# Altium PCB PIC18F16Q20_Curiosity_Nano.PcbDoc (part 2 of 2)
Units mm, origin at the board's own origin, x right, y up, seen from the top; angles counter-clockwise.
Board outline 50.8 x 20.32 mm, 4 copper layers (Top Layer, Gnd Plane, Pwr Plane, Bottom Layer), stack 1.574 mm thick; 77 components, 73 nets, 345 pads, 157 vias.
Unrouted connection lines stored in the file: 1.
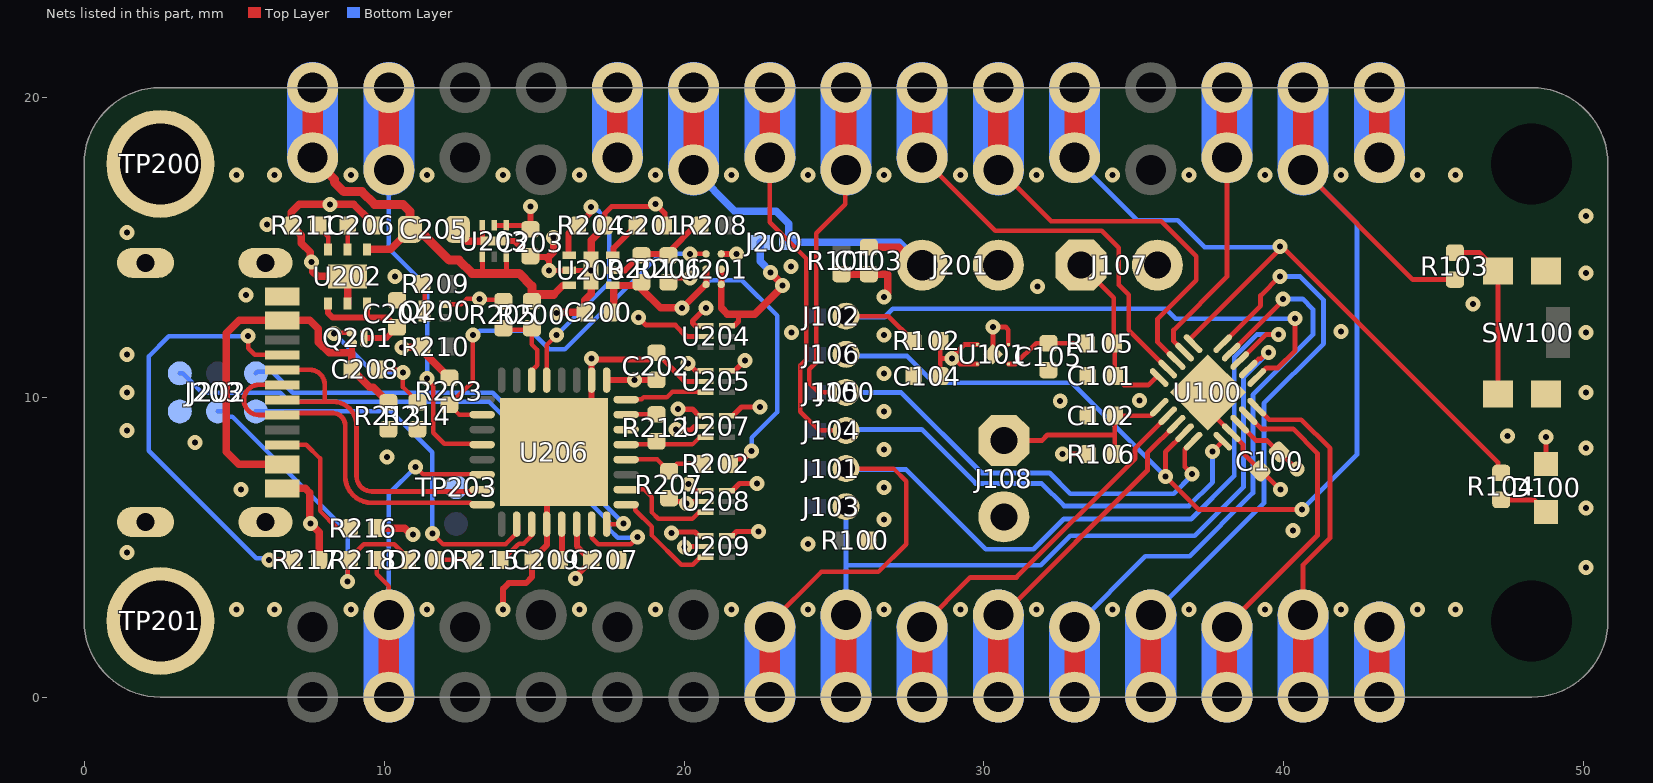
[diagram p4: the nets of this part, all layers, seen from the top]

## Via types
v1: diameter 0.5, hole 0.2, Top Layer to Bottom Layer, 147 vias
v2: diameter 0.5, hole 0.2, Top Layer to Bottom Layer, tented both sides, 8 vias
v3: diameter 0.5, hole 0.2, Top Layer to Bottom Layer, tented top, 2 vias

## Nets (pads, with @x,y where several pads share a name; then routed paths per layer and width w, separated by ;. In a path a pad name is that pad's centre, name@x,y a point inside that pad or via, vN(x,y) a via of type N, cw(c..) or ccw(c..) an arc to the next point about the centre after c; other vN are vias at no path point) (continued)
GND: C100.2 C101.2 C102.2 C103.1 C104.1 C105.1 C200.1 C201.2 C202.1 C203.1 C204.1 C205.1 C206.1 C207.2 C209.1 J100.15 J100.16 J100.26 J107.2 J108.2 J202.2 J203.1 J203.2 J203.3 J203.4 J203.A1/B12 J203.B1/A12 Q200.2 R100.2 R101.2 R203.2 R204.2 R205.1 R206.1 R207.1 R210.2 R211.2 R213.2 R214.2 R216.2 R217.2 SW100.1 SW100.2 TP200.1 TP201.1 TP203.1 U100.17 U100.21 U101.2 U101.5 U200.2 U200.7 U201.C1 U202.5 U202.7 U203.3 U203.7 U204.2 U205.2 U206.10 U206.28 U206.33 U207.2 U208.2 U209.2 | length 60
  Top Layer w0.15: Q200.2@12.04,13.1 12.575,13.1 12.75,13.275 v1(13.19,13.275) 13.215,13.25 R205.1@13.979,13.25
  Top Layer w0.16: U101.5@30.297,11.433 v1@30.297,12.325 ; v1(30.306,12.342) 30.717,12.342 30.81,12.248 U101.2@30.81,11.758 ; U100.21@37.465,10.16 37.465,9.594 38.63,8.429 38.63,8.154 39.86,6.924 v1(39.889,6.924)
  Top Layer w0.166: v1(18.48,12.65) 18.73,12.4 19.71,12.4 20.085,12.025 U204.2@20.729,12.025 ; C202.1@19.058,11.5 20.033,10.525 U205.2@20.729,10.525 ; v1(19.734,8.925) 19.759,8.9 19.804,8.9 20.217,8.9 20.343,9.025 U207.2@20.729,9.025 ; v1@20.13,5.025 U209.2@20.729,5.025 ; v1@20.155,6.525 U208.2@20.729,6.525
  Top Layer w0.175: U203.3@13.279,15.725 13.279,15.2 U203.7@13.679,15.2 ; v1(15.505,14.225) U200.2@16.18,14.225 v1(16.905,14.225) ; R204.2@17.355,15.725 17.355,16.122 17.59,16.357 18.89,16.357 18.969,16.436 v1(19.057,16.436) 19.355,16.138 C201.2@19.355,15.725 ; R206.1@19.48,13.775 19.68,13.975 v1(20.199,13.975) ; R207.1@19.555,6.525 19.559,6.521 19.861,6.521 19.932,6.45 v1(20.08,6.45) v1@20.155,6.525 ; v1(20.023,4.998) 20.103,4.998 v1@20.13,5.025 ; v1@20.089,5.025 v1@20.13,5.025 ; v1@20.125,5.02 v1@20.13,5.025
  Top Layer w0.2: U203.7@13.679,15.2 14.354,15.2 14.879,14.675 15.38,14.675 15.505,14.55 ; v1(13.97,2.921) 13.97,3.615 14.155,3.8 14.732,3.8 14.93,3.998 14.93,4.575 15.424,5.069 15.424,7.909 U206.33@15.679,8.164 ; v1(15.505,14.225) 15.505,14.55 ; 15.505,14.705 15.505,14.55 ; U206.33@15.689,8.174 16.916,9.401 16.916,11.112 17.063,11.259 18.817,11.259 C202.1@19.058,11.5 ; U201.C1@21.242,14.775 v1(21.755,14.775)
  Top Layer w0.25: J203.A1/B12@6.39,13.36 J203.A1/B12@6.665,13.36 ; J203.B1/A12@6.665,6.96 7.368,6.96 7.515,6.814 7.515,5.821 7.844,5.493 R217.2@7.844,4.575 ; U202.5@8.785,13.128 U202.7@8.785,14.028 7.784,14.028 7.627,14.186 7.627,14.452 7.535,14.544 7.535,14.84 7.246,15.128 7.246,15.393 7.081,15.558 7.062,15.558 6.913,15.707 6.913,16.168 7.172,16.426 v1(8.19,16.426) 8.192,16.424 8.986,16.424 9.518,15.892 9.536,15.892 9.685,15.743 C206.1@9.685,15.725 ; R216.2@9.752,5.633 10.684,5.633 10.892,5.425 v2(10.96,5.425) ; v1(10.599,11.649) 10.617,11.667 11.248,11.667 R210.2@11.265,11.684 11.407,11.542 11.407,11.412 12.008,10.811 12.008,10.793 12.157,10.644 R203.2@12.175,10.644 ; C205.1@12.356,15.597 12.754,15.2 U203.7@13.279,15.2 ; 15.505,14.705 15.655,14.855 v1(15.655,15.325) ; v1(15.755,12.8) 15.782,12.827 C200.1@16.695,12.827 16.695,13.233 16.905,13.443 v1(16.905,14.225) 16.905,15.225 R204.2@17.405,15.725 ; R101.2@25.248,14.104 C103.1@26.162,14.104 26.794,14.104 26.794,13.459 v1(26.67,13.335)
  other v1: 5.08,2.921 6.35,2.921 8.89,2.921 11.43,2.921 16.51,2.921 19.05,2.921 21.59,2.921 24.13,2.921 26.67,2.921 29.21,2.921 31.75,2.921 34.29,2.921 36.83,2.921 39.37,2.921 41.91,2.921 44.45,2.921 45.72,2.921 50.065,4.321 1.429,4.826 24.141,5.102 40.304,5.559 7.544,5.792 26.67,5.915 50.065,6.306 26.67,6.985 26.67,8.255 50.065,8.3 47.45,8.701 1.429,8.89 26.67,9.525 32.543,9.871 35.179,9.882 1.429,10.16 50.065,10.15 26.67,10.795 16.913,11.284 1.429,11.43 26.67,12.065 23.58,12.152 50.065,12.15 41.9,12.192 46.3,13.113 5.39,13.413 31.78,13.694 10.366,14.025 50.065,14.133 23.565,14.353 7.579,14.5 1.429,15.494 6.1,15.755 50.065,16.045 5.08,17.399 6.35,17.399 8.89,17.399 11.43,17.399 13.97,17.399 16.51,17.399 19.05,17.399 21.59,17.399 24.13,17.399 26.67,17.399 29.21,17.399 31.75,17.399 34.29,17.399 36.83,17.399 39.37,17.399 41.91,17.399 44.45,17.399 45.72,17.399
  other v2: 5.235,6.924 10.093,8.006 3.701,8.493
ID_SYS: J100.2 R218.1 U206.22 | length 9.6
  Top Layer w0.15: R218.1@9.748,4.513 9.748,4.114 10.16,3.703 J100.2@10.16,2.743 ; v1(11.055,7.675) 11.306,7.424 U206.22@13.28,7.424
  Bottom Layer w0.15: J100.2@10.16,2.743 10.16,6.78 v1(11.055,7.675)
NetC201_1: C201.1 U200.6 | length 1.3
  Top Layer w0.2: U200.6@17.655,14.725 17.655,14.975 C201.1@18.405,15.725
NetC206_2: C206.2 U202.2 | length 0.8
  Top Layer w0.15: U202.2@8.785,14.899 C206.2@8.785,15.725
NetC208_1: C208.1 Q201.1 R214.1 | length 5.5
  Top Layer w0.15: v2(8.338,12.122) 8.366,12.15 Q201.1@8.927,12.15 ; C208.1@9.818,10.931 10.431,10.931 10.536,10.825 v2(10.631,10.825) 10.631,10.339 R214.1@11.145,9.825
  Bottom Layer w0.15: v2(8.338,12.122) 9.635,10.825 v2(10.631,10.825)
NetD100_2: D100.2 R104.2 | length 1.7
  Top Layer w0.16: R104.2@47.244,6.573 48.342,6.573 D100.2@48.74,6.175
NetD200_2: D200.2 R215.1 | length 1.3
  Top Layer w0.15: D200.2@11.715,4.575 R215.1@12.98,4.575
NetJ203_A5: J203.A5 R217.1 | length 14.7
  Top Layer w0.15: v2(5.468,12.035) 5.468,11.634 5.691,11.41 J203.A5@6.665,11.41 ; v2(6.165,4.575) R217.1@6.944,4.575
  Bottom Layer w0.15: v2(5.468,12.035) 2.827,12.035 2.15,11.358 2.15,8.219 5.737,4.632 6.108,4.632 v2(6.165,4.575)
NetJ203_B5: J203.B5 R216.1 | length 4.4
  Top Layer w0.15: J203.B5@6.665,8.41 7.411,8.41 7.865,7.956 7.865,6.208 8.44,5.633 R216.1@8.852,5.633
NetQ200_3: Q200.3 R209.1 | length 1
  Top Layer w0.15: R209.1@11.214,13.7 11.355,13.559 Q200.3@11.355,12.8
NetR103_2: R103.2 SW100.3 SW100.4 | length 5.8
  Top Layer w0.16: R103.2@45.7,14.821 46.519,14.821 46.72,14.62 46.72,14.57 47.09,14.2 SW100.4@47.14,14.2 SW100.3@47.14,10.1
NetR211_1: R211.1 U202.3 | length 0.9
  Top Layer w0.15: R211.1@7.813,15.725 7.813,15.666 8.135,15.344 U202.3@8.135,14.912
RA0_ANA0_ICSPDAT: J100.24 J104.2 U100.16 | length 26
  Top Layer w0.15: J100.24@22.86,17.983 22.86,15.836 24.075,14.621 24.075,11.251 23.88,11.056 23.88,9.518 24.508,8.89 J104.2@25.4,8.89
  Top Layer w0.16: v1(37.619,8.193) U100.16@37.96,8.534
  Bottom Layer w0.16: J104.2@25.4,8.89 25.434,8.924 27.921,8.924 29.72,7.125 31.917,7.125 32.669,6.373 34.816,6.373 34.82,6.377 36.83,6.377 37.619,7.166 v1(37.619,8.193)
RA1_ANA1_ICSPCLK: J100.23 J105.2 U100.15 | length 23.5
  Top Layer w0.15: J105.2@25.4,10.16 24.487,10.16 24.18,10.467 24.18,10.932 24.403,11.155 24.403,15.463 25.375,16.434 25.375,17.551 J100.23@25.4,17.577
  Top Layer w0.16: v1(36.935,7.432) 36.692,7.675 36.692,8.256 U100.15@36.97,8.534
  Bottom Layer w0.16: J105.2@25.4,10.16 25.407,10.153 27.24,10.153 29.921,7.472 32.19,7.472 32.881,6.781 34.034,6.781 36.321,6.781 36.935,7.395 v1(36.935,7.432)
RA2_ANA2_DBG2_SW0_INT0: J100.17 J106.2 R103.1 U100.14 | length 38.5
  Top Layer w0.16: v1(36.048,7.359) 37.147,6.26 v1(40.604,6.26) ; v1@36.051,7.359 36.051,8.18 U100.14@36.687,8.816 ; J100.17@40.64,17.577 44.296,13.921 R103.1@45.7,13.921
  Bottom Layer w0.16: J106.2@25.4,11.43 25.455,11.375 27.432,11.375 28.328,10.478 32.929,10.478 v1(36.048,7.359) ; v1(40.604,6.26) 42.436,8.092 42.436,15.78 J100.17@40.64,17.577
RA3_M\C\L\R\: J102.2 R102.1 U100.1 | length 20.5
  Top Layer w0.16: J102.2@25.4,12.7 26.814,12.7 R102.1@27.639,11.875 ; U100.1@39.091,10.655 39.409,10.972 39.798,10.972 40.373,11.547 v1(40.373,12.616)
  Bottom Layer w0.16: J102.2@25.4,12.7 25.431,12.669 26.683,12.669 26.964,12.95 36.052,12.95 36.387,12.616 v1(40.373,12.616)
RA4_SPI_SS: J100.14 U100.20 | length 8.9
  Top Layer w0.16: U100.20@39.091,9.665 39.506,9.25 40.579,9.25 41.537,8.293 41.537,5.309 40.64,4.413 J100.14@40.64,2.743
RA5_SPI_SCK: J100.13 U100.19 | length 9.9
  Top Layer w0.16: J100.13@38.1,2.337 38.1,2.371 41.117,5.389 41.117,8.127 40.304,8.94 39.251,8.94 U100.19@38.809,9.382
RB5_I3C2_SDA: J100.22 U100.9 | length 12.5
  Top Layer w0.16: J100.22@27.94,17.983 30.377,15.546 33.926,15.546 34.496,14.977 34.496,13.742 34.829,13.409 34.829,12.23 U100.9@36.121,10.938
RB6_I3C2_SCL: J100.21 U100.8 | length 12.1
  Top Layer w0.16: J100.21@30.48,17.577 30.527,17.577 32.237,15.867 35.91,15.867 37.077,14.7 37.077,13.898 35.782,12.602 35.782,11.843 U100.8@36.404,11.221
RB7_ANB7: J100.18 U100.7 | length 7.4
  Top Layer w0.16: U100.7@36.687,11.504 36.323,11.868 36.323,12.238 38.1,14.015 J100.18@38.1,18
RC0_I2C_I3C1_SCL: J100.10 U100.13 | length 8.9
  Top Layer w0.16: J100.10@30.48,2.743 30.637,2.743 35.45,7.556 35.45,8.145 U100.13@36.404,9.099
RC1_I2C_I3C1_SDA: J100.9 U100.12 | length 11.3
  Top Layer w0.16: J100.9@27.94,2.337 27.94,2.385 29.548,3.993 31.082,3.993 35.039,7.95 35.039,8.299 U100.12@36.121,9.382
RC3_SPI_MOSI: J100.11 U100.4 | length 18.4
  Top Layer w0.16: U100.4@38.243,11.504 39.976,13.237 v1(39.976,13.274)
  Bottom Layer w0.16: J100.11@33.02,2.337 35.379,4.696 36.854,4.696 38.966,6.807 38.966,10.08 40.965,12.08 40.965,12.932 40.623,13.274 v1(39.976,13.274)
RC4_UART_TX: J100.7 J101.2 U100.3 | length 32.5
  Top Layer w0.15: J100.7@22.86,2.337 22.86,2.461 24.572,4.173 26.479,4.173 27.404,5.099 27.404,7.202 26.986,7.62 J101.2@25.4,7.62 J101.2@25.41,7.61
  Top Layer w0.16: U100.3@38.526,11.221 39.394,12.089 v1(39.817,12.089)
  Bottom Layer w0.16: J101.2@25.4,7.62 25.427,7.593 27.399,7.593 30.059,4.932 31.65,4.932 32.657,5.939 36.911,5.939 38.346,7.374 38.346,11.337 39.097,12.089 v1(39.817,12.089)
RC5_UART_RX: J100.8 J103.2 U100.2 | length 23.7
  Top Layer w0.16: U100.2@38.809,10.938 39.154,11.284 39.234,11.284 39.444,11.494 v1(39.491,11.494)
  Bottom Layer w0.16: J100.8@25.4,2.743 25.4,4.4 ; J103.2@25.4,6.35 25.4,4.4 ; v1(39.491,11.494) 38.656,10.659 38.656,7.01 37.028,5.383 32.874,5.383 31.891,4.4 25.4,4.4
RC6_SPI_MISO: J100.12 U100.5 | length 17.7
  Top Layer w0.16: U100.5@37.96,11.786 39.222,13.048 39.222,13.385 v1(39.864,14.028)
  Bottom Layer w0.16: J100.12@35.56,2.743 35.606,2.743 39.332,6.469 39.332,9.793 41.323,11.784 41.323,13.236 40.531,14.028 v1(39.864,14.028)
RC7_ANC7_LED0_PWM: J100.20 R104.1 U100.6 | length 23.3
  Top Layer w0.16: U100.6@36.97,11.786 36.856,11.9 36.856,11.926 39.876,14.946 v1(39.876,15.02) 39.943,15.02 47.135,7.828 47.135,7.582 R104.1@47.244,7.473
  Bottom Layer w0.16: J100.20@33.02,17.983 35.106,15.897 36.457,15.897 37.354,15 39.856,15 v1(39.876,15.02)
REG_ADJUST: R201.2 R206.2 R208.1 U200.5 | length 3.4
  Top Layer w0.2: U200.5@17.655,14.225 18.03,14.225 18.58,14.775 19.505,14.775 19.505,14.85 R208.1@20.38,15.725
REG_ENABLE: R204.1 U200.1 U206.13 | length 8.9
  Top Layer w0.15: U206.13@15.416,10.556 15.416,11.736 v1(15.755,12.075)
  Top Layer w0.2: U200.1@16.155,14.725 16.155,15.475 16.405,15.725 R204.1@16.373,15.725 ; R204.1@16.455,15.725 16.455,15.73 16.65,15.925 16.655,15.925 16.848,16.118 16.848,16.275 v1(16.905,16.333)
  Bottom Layer w0.15: v1(15.755,12.075) 17.506,13.826 17.506,15.853 17.151,16.207 17.125,16.207 17,16.333 v1(16.905,16.333)
RESERVED: U206.6
S0_0_RX: R212.1 U206.5 U207.3 | length 2.8
  Top Layer w0.15: U206.5@18.06,8.424 20.28,8.424 20.531,8.675 U207.3@20.729,8.675
S0_2_TX: R212.2 U206.7 | length 1
  Top Layer w0.15: U206.7@18.06,9.424 R212.2@19.055,9.424
S0_3_CLK: U205.3 U206.8 | length 2.8
  Top Layer w0.15: U206.8@18.06,9.937 18.595,9.937 18.659,10 19.43,10 19.605,10.175 U205.3@20.729,10.175
S1_0_TX: U206.1 U209.3 | length 3.9
  Top Layer w0.15: U206.1@18.07,6.42 18.33,6.42 18.376,6.374 18.376,6.231 18.93,5.677 18.93,5.389 19.906,4.413 20.291,4.413 20.554,4.675 U209.3@20.729,4.675
S1_1_RX: U206.2 U208.3 | length 3.5
  Top Layer w0.15: U206.2@18.06,6.924 18.666,6.924 18.93,6.66 18.93,6.156 19.136,5.95 20.28,5.95 20.505,6.175 U208.3@20.729,6.175
S\R\S\T\: J202.6 U206.26 | length 12.5
  Top Layer w0.15: v3(11.609,5.458) 11.967,5.1 13.102,5.1 14.05,5.1 14.465,5.515 14.465,5.55 14.47,5.555 U206.26@14.47,5.695
  Bottom Layer w0.15: J202.6@5.73,9.525 10.245,9.524 11.609,8.16 v3(11.609,5.458)
STATUS_LED: R215.2 U206.27 | length 1.7
  Top Layer w0.15: R215.2@13.93,4.575 13.955,4.575 14.455,5.075 14.5,5.12 14.66,5.12 14.765,5.225 14.933,5.393 U206.27@14.933,5.777
SWCLK: J202.1 U206.31 | length 19.9
  Top Layer w0.15: U206.31@16.924,5.787 16.924,5.316 17.14,5.1 18.224,5.1 v1(18.455,5.331)
  Bottom Layer w0.15: J202.1@3.19,10.795 3.285,10.795 3.93,10.15 6.536,10.15 6.833,9.853 13.496,9.853 17.514,5.835 17.514,5.587 17.792,5.309 18.433,5.309 v1(18.455,5.331)
SWDIO: J202.5 U206.32 | length 14.9
  Top Layer w0.15: U206.32@17.42,5.77 17.975,5.77 v1(17.989,5.784)
  Bottom Layer w0.15: J202.5@5.73,10.795 5.778,10.843 6.267,10.843 6.958,10.153 13.62,10.153 v1(17.989,5.784)
USBD_N: J203.A7 J203.B7 U206.23 | length 13
  Top Layer w0.16: J203.B7@6.665,10.91 6.669,10.914 7.523,10.914 ; U206.23@13.27,6.92 12.946,6.92 12.886,6.86 9.59,6.86 ; J203.A7@6.725,9.85 cw(c6.725,9.91) 6.665,9.91 ccw(c6.725,9.91) J203.A7@6.725,9.85 ; J203.A7@6.725,9.85 8.025,9.85 ; 7.522,10.914 cw(c7.522,10.414) 8.022,10.414 ; 7.522,10.914 cw(c7.522,10.414) 8.022,10.414 ; 8.022,10.414 8.022,9.852 8.025,9.85 ; 8.025,9.85 8.296,9.85 cw(c8.296,9.063) 9.083,9.063 9.083,7.366 ; 9.083,7.366 ccw(c9.59,7.366) 9.59,6.86 ; 9.083,7.366 ccw(c9.59,7.366) 9.59,6.86
USBD_P: J203.A6 J203.B6 U206.24 | length 15.3
  Top Layer w0.16: 5.327,9.912 cw(c5.827,9.912) 5.827,10.412 J203.A6@6.665,10.412 ; U206.24@13.27,6.42 12.946,6.42 12.886,6.48 9.59,6.48 ; 5.827,9.408 cw(c5.827,9.908) 5.327,9.908 ccw(c5.827,9.908) 5.827,9.408 ; 5.827,9.408 6.665,9.408 J203.B6@6.665,9.41 ; J203.B6@6.665,9.41 cw(c6.725,9.41) J203.B6@6.725,9.47 ; J203.B6@6.665,9.41 cw(c6.725,9.41) J203.B6@6.725,9.47 ; J203.B6@6.725,9.47 8.296,9.47 ; 8.296,9.47 cw(c8.296,9.063) 8.703,9.063 ; 8.296,9.47 cw(c8.296,9.063) 8.703,9.063 ; 8.703,7.366 ccw(c9.59,7.366) 9.59,6.48 ; 8.703,7.366 ccw(c9.59,7.366) 9.59,6.48 ; 8.703,7.366 8.703,9.063
V\O\F\F\: J100.29 U206.20 | length 11.2
  Top Layer w0.15: v1(11.433,10.628) 11.433,10.573 11.635,10.371 11.635,8.815 12.003,8.447 12.873,8.447 12.88,8.439 13.251,8.439 U206.20@13.27,8.42
  Bottom Layer w0.15: J100.29@10.16,17.577 10.16,14.958 11.433,13.686 v1(11.433,10.628)
VBUS: C208.2 J203.A4/B9 J203.B4/A9 Q201.2 R213.1 | length 13.6
  Top Layer w0.2: 8.927,11.475 Q201.2@8.927,11.715
  Top Layer w0.25: J203.B4/A9@6.675,7.76 6.665,7.76 5.16,7.76 4.74,8.18 4.74,12.131 5.169,12.56 6.665,12.56 7.528,12.56 7.813,12.275 7.813,11.832 8.171,11.475 8.927,11.475 C208.2@8.927,10.94 ; C208.2@8.918,10.931 8.918,10.912 9.067,10.763 9.085,10.763 9.523,10.325 9.644,10.325 9.976,9.992 9.976,9.974 10.121,9.829 R213.1@10.139,9.829
VBUS_ADC: R200.2 R205.2 U206.14 | length 2.8
  Top Layer w0.15: R205.2@13.979,12.25 14.916,12.25 14.916,11.764 15.105,11.575 15.105,11.068 14.916,10.879 U206.14@14.916,10.556
VBUS_DELAYED: C204.2 Q201.3 U202.4 U202.6 | length 4.5
  Top Layer w0.2: U202.4@8.135,13.128 8.135,13.054 8.135,12.803 8.286,12.652 10.108,12.652 10.266,12.494 10.266,12.476 C204.2@10.415,12.327 ; Q201.3@9.41,11.975 10.082,11.975 10.266,12.16 10.266,12.178 C204.2@10.415,12.327 ; U202.6@9.435,13.128 9.435,12.669 9.437,12.667 ; C204.2@10.434,12.327 C204.2@10.415,12.327
VCC_EDGE: C103.2 J100.25 J200.2 J201.1 | length 11.5
  Top Layer w0.25: C103.2@26.162,15.004 27.163,15.004 27.766,14.402 J201.1@27.94,14.402 ; J201.1@27.786,14.402 J201.1@27.94,14.402
  Bottom Layer w0.25: J100.25@20.32,17.577 21.694,16.203 23.074,16.203 23.49,15.787 J200.2@23.49,15.162 27.18,15.162 J201.1@27.94,14.402
VCC_LEVEL: J200.1 U201.A1 U201.B1 U204.6 U205.6 U207.6 U208.6 U209.6 | length 10.5
  Top Layer w0.175: U209.6@21.429,5.375 21.605,5.375 21.755,5.525 v1(22.48,5.525) ; U208.6@21.429,6.875 21.605,6.875 21.855,7.125 v1(22.43,7.125) ; U207.6@21.429,9.375 21.442,9.388 21.627,9.388 21.915,9.675 v1(22.53,9.675) ; U205.6@21.429,10.875 21.68,10.875 v1(22.03,11.225) ; U204.6@21.429,12.375 21.442,12.388 21.677,12.388 21.815,12.525 21.815,12.767
  Top Layer w0.2: U201.A1@21.242,13.775 U201.B1@21.242,14.267
  Top Layer w0.225: 21.242,12.963 U201.A1@21.242,13.759 U201.A1@21.242,13.775
  Top Layer w0.25: 21.254,12.963 21.449,12.767 21.815,12.767 22.362,12.767 23.29,13.695 v1(23.29,13.725) 23.29,13.745 v1(22.876,14.159)
  Bottom Layer w0.25: J200.1@22.54,15.162 22.54,14.525 22.876,14.189 v1(22.876,14.159)
VCC_MCU_CORE: C209.2 U206.29 | length 1.2
  Top Layer w0.2: C209.2@15.88,4.575 15.924,4.619 U206.29@15.924,5.787
VCC_P3V3: C202.2 C203.2 C207.1 D200.1 J202.4 R218.2 U203.1 U203.2 U204.1 U205.1 U206.9 U206.30 U207.1 U208.1 U209.1 | length 21.8
  Top Layer w0.15: v1(8.785,3.855) 8.785,4.511 R218.2@8.848,4.575 8.848,4.625 9.323,5.1 10.34,5.1 10.815,4.625 D200.1@10.815,4.575
  Top Layer w0.175: U203.2@13.679,15.725 14.779,15.725 C203.2@14.879,15.625 ; v1(19.581,5.475) 19.613,5.507 20.363,5.507 20.483,5.388 20.717,5.388 20.729,5.375 U209.1@20.508,5.375 ; v1(19.804,9.6) 20.28,9.6 20.505,9.375 U207.1@20.729,9.375 ; v1(20.139,11.125) 20.389,10.875 U205.1@20.729,10.875 ; v1(20.155,7.1) 20.38,6.875 U208.1@20.729,6.875 ; U204.1@20.729,12.375 20.383,12.375 20.28,12.478 20.28,12.541 20.712,12.973 v1(20.729,12.973)
  Top Layer w0.2: C203.2@14.879,15.6 v1(14.879,16.357) ; v1(16.375,3.95) 16.375,4.009 16.905,4.539 C207.1@16.905,4.575 ; U206.30@16.424,5.787 16.424,5.031 C207.1@16.88,4.575 ; U206.9@17.416,10.581 v1(18.355,10.581) 18.969,10.581 C202.2@19.055,10.495
  Bottom Layer w0.15: J202.4@4.46,9.525 4.636,9.525 4.813,9.348 4.946,9.348 8.786,5.508 v1(8.785,3.855)
VCC_REGULATOR: C200.2 R201.1 R202.2 U200.4 U201.A2 U201.B2 | length 23.7
  Top Layer w0.175: R202.2@21.579,7.875 21.653,7.95 22.005,7.95 v1(22.255,8.2) ; v1@22.305,8.175 v1@22.33,8.2
  Top Layer w0.2: R201.1@18.58,13.62 R201.1@18.58,13.775 ; U201.A2@20.742,13.775 U201.B2@20.742,14.275
  Top Layer w0.225: v1(19.94,12.973) U201.A2@20.742,13.775
  Top Layer w0.24: C200.2@17.655,13.02 17.655,13.725 18.53,13.725 R201.1@18.58,13.775
  Top Layer w0.25: R201.1@18.58,13.62 19.227,12.973 v1(19.94,12.973)
  Bottom Layer w0.15: 20.867,13.9 21.927,13.9 ; 20.867,13.9 21.927,13.9 ; 20.867,13.9 v1(19.94,12.973) 20.867,13.9 ; 21.927,13.9 23.105,12.722 ; 21.927,13.9 23.105,12.722 ; 22.255,8.654 v1(22.255,8.2) 22.255,8.654 ; 22.255,8.654 23.105,9.504 ; 22.255,8.654 23.105,9.504 ; 23.105,9.504 23.105,12.722 ; 23.105,9.504 23.105,12.722
VCC_TARGET: C100.1 C104.2 D100.1 J201.2 R102.2 R106.2 U100.18 U101.3 U101.4 | length 7.9
  Top Layer w0.159: C100.1@39.817,8.175 C100.1@39.84,8.175
  Top Layer w0.16: R102.2@28.539,11.875 28.539,11.29 ; C104.2@28.555,10.701 28.539,10.716 28.539,11.29 ; U101.4@29.784,11.108 29.195,11.108 29.013,11.29 v1(28.931,11.29) ; U101.3@29.784,11.758 29.354,11.758 29.02,11.423 29.02,11.339 29.069,11.29 v1(28.931,11.29) ; v1(32.618,8.105) R106.2@33.458,8.105 ; U100.18@38.526,9.099 39.073,8.552 39.44,8.552 C100.1@39.817,8.175 ; C100.1@39.84,8.175 40.388,7.628 v1@40.388,7.618 ; D100.1@48.74,7.775 v1(48.74,8.671) ; 28.539,11.29 v1(28.931,11.29)
  other v1: 40.432,7.61
VCC_VBUS: C205.2 J100.30 R200.1 U200.3 U202.1 U203.4 U203.6 | length 14
  Top Layer w0.175: 13.279,14.151 U203.4@13.279,14.675 ; 14.079,14.151 U203.6@14.079,14.675
  Top Layer w0.24: 15.655,13.425 15.955,13.725 U200.3@16.155,13.725
  Top Layer w0.25: U202.1@9.455,14.928 10.218,14.928 C205.2@10.858,15.569
  Top Layer w0.3: J100.30@7.62,17.983 8.34,17.263 8.34,17.171 8.662,16.849 9.26,16.849 9.683,16.426 10.629,16.426 10.858,16.197 C205.2@10.858,15.597 10.909,15.546 11.067,15.388 11.358,15.388 12.175,14.571 12.493,14.571 12.939,14.125 14.504,14.125 14.929,13.7 R200.1@14.929,13.425 ; R200.1@14.929,13.25 R200.1@14.929,13.425 ; 15.655,13.425 R200.1@14.929,13.425
VCC_VDDIO3_P1V2: C105.2 R105.2 U101.1 | length 2.9
  Top Layer w0.16: U101.1@30.81,11.108 31.05,11.108 31.742,11.8 C105.2@32.149,11.8 33.426,11.8 R105.2@33.429,11.797
VDDIO2: C102.1 J108.1 R106.1 U100.11 | length 6.6
  Top Layer w0.16: J108.1@30.663,8.552 31.929,8.552 32.116,8.739 34.358,8.739 ; R106.1@34.358,8.105 34.358,8.739 ; U100.11@35.839,9.665 35.556,9.382 C102.1@34.367,9.382 34.358,9.374 34.358,8.739
VDDIO3: C101.1 J107.1 R105.1 U100.10 | length 5.9
  Top Layer w0.16: J107.1@33.242,14.402 34.329,13.314 R105.1@34.329,11.797 34.358,11.768 C101.1@34.358,10.713 34.669,10.401 35.477,10.401 35.772,10.696 35.798,10.696 U100.10@35.839,10.655
VTG_ADC: R202.1 R207.2 U206.4 | length 2.7
  Top Layer w0.15: U206.4@18.06,7.924 19.11,7.924 R207.2@19.505,7.529 ; R207.2@19.543,7.561 19.756,7.775 R202.1@20.579,7.775
VTG_EN: R203.1 U201.C2 U206.18 | length 13.3
  Top Layer w0.15: v1(12.965,12.075) 12.965,10.534 R203.1@12.175,9.744 12.499,9.42 U206.18@13.27,9.42 ; v1(20.199,14.775) U201.C2@20.742,14.775
  Bottom Layer w0.15: v1(12.965,12.075) 13.06,12.075 13.195,12.211 14.894,12.211 15.505,11.6 16.03,11.6 19.205,14.775 v1(20.199,14.775)
pads on no net: J100.1 J100.19 J202.3 J203.0 J203.A8 J203.B8 Q200.0 Q201.0 SW100.5 U202.0 U203.5

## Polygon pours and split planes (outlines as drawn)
GND on Bottom Layer "Bottom Layer-GND" (solid, remove dead copper, pour order 1): 83.82,20.32 83.82,0 0,0 0,20.32
GND on Top Layer "Top Layer-GND" (solid, remove dead copper, pour order 0): 50.8,20.32 50.8,0 0,0 0,20.32
VCC_P3V3 on Pwr Plane (split plane): 2.54,19.81 21.461,19.81 21.461,14.6 21.461,4.95 21.461,0.51 2.54,0.51 2.524,0.509 2.341,0.518 2.144,0.547 1.95,0.596 1.762,0.663 1.582,0.748 1.411,0.851 1.251,0.969 1.103,1.103 0.969,1.251 0.851,1.411 0.748,1.582 0.663,1.762 0.596,1.95 0.547,2.144 0.518,2.341 0.509,2.524 0.51,2.54 0.51,17.78 0.509,17.796 0.518,17.979 0.547,18.176 0.596,18.37 0.663,18.558 0.748,18.738 0.851,18.909 0.969,19.069 1.103,19.217 1.251,19.351 1.411,19.469 1.582,19.572 1.762,19.657 1.95,19.724 2.144,19.773 2.341,19.802 2.524,19.811
VCC_TARGET on Pwr Plane (split plane): 48.459,19.802 48.656,19.773 48.85,19.724 49.038,19.657 49.218,19.572 49.389,19.469 49.549,19.351 49.697,19.217 49.831,19.069 49.949,18.909 50.052,18.738 50.137,18.558 50.204,18.37 50.253,18.176 50.282,17.979 50.291,17.796 50.29,17.78 50.29,2.54 50.291,2.524 50.282,2.341 50.253,2.144 50.204,1.95 50.137,1.762 50.052,1.582 49.949,1.411 49.831,1.251 49.697,1.103 49.549,0.969 49.389,0.851 49.218,0.748 49.038,0.663 48.85,0.596 48.656,0.547 48.459,0.518 48.276,0.509 48.26,0.51 21.719,0.51 21.719,4.821 24.255,4.821 24.305,4.83 24.347,4.858 24.375,4.9 24.384,4.95 24.384,14.6 24.375,14.65 24.347,14.692 24.305,14.72 24.255,14.729 21.719,14.729 21.719,19.81 48.26,19.81 48.276,19.811
VCC_LEVEL on Pwr Plane (split plane): 24.126,5.079 21.719,5.079 21.719,14.47 24.126,14.47
GND on Gnd Plane (split plane): 48.459,19.802 48.656,19.773 48.85,19.724 49.038,19.657 49.218,19.572 49.389,19.469 49.549,19.351 49.697,19.217 49.831,19.069 49.949,18.909 50.052,18.738 50.137,18.558 50.204,18.37 50.253,18.176 50.282,17.979 50.291,17.796 50.29,17.78 50.29,2.54 50.291,2.524 50.282,2.341 50.253,2.144 50.204,1.95 50.137,1.762 50.052,1.582 49.949,1.411 49.831,1.251 49.697,1.103 49.549,0.969 49.389,0.851 49.218,0.748 49.038,0.663 48.85,0.596 48.656,0.547 48.459,0.518 48.276,0.509 48.26,0.51 2.54,0.51 2.524,0.509 2.341,0.518 2.144,0.547 1.95,0.596 1.762,0.663 1.582,0.748 1.411,0.851 1.251,0.969 1.103,1.103 0.969,1.251 0.851,1.411 0.748,1.582 0.663,1.762 0.596,1.95 0.547,2.144 0.518,2.341 0.509,2.524 0.51,2.54 0.51,17.78 0.509,17.796 0.518,17.979 0.547,18.176 0.596,18.37 0.663,18.558 0.748,18.738 0.851,18.909 0.969,19.069 1.103,19.217 1.251,19.351 1.411,19.469 1.582,19.572 1.762,19.657 1.95,19.724 2.144,19.773 2.341,19.802 2.524,19.811 2.54,19.81 48.26,19.81 48.276,19.811

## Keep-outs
Bottom Layer:
  rectangle: 27.94,13.552 30.48,15.252
  region: 23.655,14.69 23.655,15.666 22.282,15.666 22.282,14.69
Keep-Out Layer:
  text "'.Layer_Name'" at 174.01,-104.74 h1.5

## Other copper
Top Layer:
  pour cut-out: 29.463,10.783 31.126,10.783 31.126,12.083 29.462,12.083
  region net GND: 19.741,6.67 19.768,6.697 19.798,6.702 19.809,6.678 19.821,6.662 19.835,6.642 19.845,6.632 19.863,6.618 19.886,6.613 19.901,6.616 19.912,6.604 19.916,6.584 19.881,6.538 19.756,6.522 19.711,6.568
  region net VTG_ADC: 19.795,7.658 19.774,7.712 19.88,7.706 19.853,7.699 19.831,7.69 19.813,7.675
  region net GND: 18.724,11.343 18.794,11.413 18.825,11.343
  text ".ProjectPCBFabRevision" at 209.188,-104.562 h1.5
  text "'.Layer_Name'" at 174.01,-104.74 h1.5
Bottom Layer:
  pour cut-out: 25.99,13.356 25.99,5.694 23.875,5.694 23.875,13.356
  region net DBG0: 24.332,8.448 24.403,8.578 24.543,8.578 24.643,8.448
  text ".ProjectPCBFabRevision" at 209.188,-104.562 h1.5
  text ".ProjectPCBFabRevision" at 209.188,-104.562 h1.5
  text ".ProjectPCBFabRevision" at 209.188,-104.562 h1.5
  text "'.Layer_Name'" at 174.01,-104.74 h1.5
Pwr Plane (plane layer: these items are gaps in the copper):
  lines w0.254: 21.59,0.016 21.59,4.95 ; 21.59,20.32 21.59,14.6 ; 21.59,4.95 21.59,14.6 ; 21.59,4.95 24.255,4.95 24.255,14.6 21.59,14.6

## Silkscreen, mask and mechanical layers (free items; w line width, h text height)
Top Overlay:
  lines w0.15: 6.699,3.989 21.364,3.989 ; 6.699,16.306 21.391,16.306 ; 17.525,16.75 18.025,16.75 ; 18.975,16.75 19.475,16.75 ; 19.225,16.5 19.225,17 ; 28.863,6.01 29.363,6.01 ; 28.863,8.54 29.363,8.54 ; 29.113,8.29 29.113,8.79 ; 33.042,12.736 33.542,12.736 ; 33.292,12.486 33.292,12.986 ; 35.563,12.684 36.063,12.684
  text "GND" at 5.497,16.58 h0.9 r90
  text "RA0" at 21.905,16.086 h0.75
  text "RB5" at 26.968,15.972 h0.75
  text "RC7" at 32.045,15.972 h0.75
  text "RB7" at 37.125,15.972 h0.75
  text "GND" at 42.205,15.972 h0.75
  text "RA1" at 24.55,15.693 h0.75
  text "RB6" at 29.508,15.693 h0.75
  text "NC" at 34.96,15.693 h0.75
  text "RA2" at 39.665,15.693 h0.75
  text "RA2" at 46.965,15.208 h0.75
  text "VDDIO3" at 37.366,14.25 h0.75
  text "POWER" at 27.551,12.452 h0.75
  text "SW0" at 46.05,11.185 h0.75 r90
  text "1.2V" at 29.211,9.92 h0.7
  text "DEBUGGER" at 8.35,6.697 h0.75 r90
  text "PIC® / MCU" at 40.64,6.561 h2.2
  text "c" at 40.067,6.423 h8
  text "LED0" at 46.05,5.476 h0.75 r90
  text "'.ProjectTargetName'" at 33.175,5.2 h0.9
  text "PS" at 10.66,5.175 h0.75
  text "VDDIO2" at 28.479,5.122 h0.75 r90
  text "'.ProjectTargetName' / CURIOSITY NANO" at 24.63,4.802 h1.35 r90
  text "RC7" at 46.965,4.405 h0.75
  text "RC5" at 24.425,3.912 h0.75
  text "RC0" at 29.508,3.912 h0.75
  text "RC6" at 34.585,3.912 h0.75
  text "RA4" at 39.665,3.912 h0.75
  text "RC4" at 21.885,3.609 h0.75
  text "RC1" at 27.093,3.609 h0.75
  text "RC3" at 32.045,3.609 h0.75
  text "RA5" at 37.125,3.609 h0.75
  text "GND" at 42.205,3.609 h0.75
  text "GND" at 5.497,1.34 h0.9 r90
  text ".ProjectPCBFabRevision" at 209.188,-104.562 h1.5
  text "'.Layer_Name'" at 174.01,-104.74 h1.5
Bottom Overlay:
  lines w0.15: 23.815,5.625 23.815,13.42 ; 26.115,5.625 26.115,13.42 ; 27.365,13.42 26.115,13.42 20.54,13.42 20.54,5.625 29.165,5.625 29.165,13.42 28.515,13.42
  lines w0.2: 31.1,9.9 31.3,9.9 31.2,10 ; 31.3,11.15 31.3,10.2 31,9.9 31,10.2 31.2,10 ; 31.7,13.574 32,13.874 32,13.574 31.8,13.774 ; 31.9,13.874 31.7,13.874 31.8,13.774 ; 31.2,10 31.2,10 ; 31.8,13.774 31.8,13.774
  text "GND" at 5.497,18.98 h0.9 r90
  text "VBUS" at 8.375,16.025 h0.75
  text "D3" at 13.325,15.972 h0.75
  text "GND" at 18.78,15.972 h0.75
  text "RA0" at 23.86,15.947 h0.75
  text "RB5" at 28.94,15.947 h0.75
  text "RC7" at 34.02,15.947 h0.75
  text "RB7" at 39.1,15.947 h0.75
  text "GND" at 44.18,15.947 h0.75
  text "VOFF" at 11.535,15.693 h0.75
  text "D0" at 15.865,15.693 h0.75
  text "VTG" at 21.32,15.693 h0.75
  text "RA1" at 26.275,15.668 h0.75
  text "RB6" at 31.48,15.668 h0.75
  text "NC" at 36.185,15.668 h0.75
  text "RA2" at 41.64,15.668 h0.75
  text "CONNECTIONS" at 26.711,13.774 h0.7
  text "'.ProjectPCBFabNumber' Rev'.ProjectPCBFabRevision'" at 50.2,13.686 h2
  text "TARGET" at 30.2,13.5 h0.7 r90
  text "VDDIO3" at 35.164,12.45 h0.75
  text "DEBUGGER" at 20.205,12.397 h0.75 r90
  text "D3" at 23.485,12.335 h0.75
  text "RA3" at 28.684,12.33 h0.75
  text "VDDIO2" at 35.143,11.4 h0.75
  text "Microchip © 2023" at 50.5,11.15 h2
  text "D2" at 23.485,11.06 h0.75
  text "RA2" at 28.672,11.054 h0.75
  text "C" at 19.2,10.8 h9.7
  text "" at 12.911,10.48 h5 r90
  text "4" at 12.356,10.467 h5
  text "D1" at 23.485,9.785 h0.75
  text "RA1" at 28.672,9.779 h0.75
  text "D0" at 23.485,8.51 h0.75
  text "RA0" at 28.672,8.504 h0.75
  text "CDC" at 21.719,7.985 h0.75 r90
  text "RX" at 23.485,7.235 h0.75
  text "RC4" at 28.672,7.229 h0.75
  text "GND" at 11.5,6.655 h0.75
  text "TX" at 23.485,5.96 h0.75
  text "RC5" at 28.672,5.954 h0.75
  text "1" at 18.776,5.7 h5
  text "BOOT" at 11.5,5.41 h0.75
  text "CDC" at 14.955,4.825 h0.75
  text "ID" at 10.722,3.913 h0.75
  text "TX" at 15.865,3.913 h0.75
  text "D2" at 20.945,3.913 h0.75
  text "RC5" at 26.4,3.887 h0.75
  text "RC0" at 31.48,3.887 h0.75
  text "RC6" at 36.56,3.887 h0.75
  text "RA4" at 41.64,3.887 h0.75
  text "GND" at 5.497,3.74 h0.9 r90
  text "RC4" at 23.86,3.584 h0.75
  text "RC1" at 28.815,3.584 h0.75
  text "RC3" at 34.02,3.584 h0.75
  text "RA5" at 39.1,3.584 h0.75
  text "GND" at 44.18,3.584 h0.75
  text "NC" at 8.245,3.534 h0.75
  text "RX" at 13.325,3.534 h0.75
  text "D1" at 18.28,3.534 h0.75
  text ".ProjectPCBFabRevision" at 209.188,-104.562 h1.5
  text "'.Layer_Name'" at 174.01,-104.74 h1.5
Top Paste:
  text ".ProjectPCBFabRevision" at 209.188,-104.562 h1.5
  text "'.Layer_Name'" at 174.01,-104.74 h1.5
Bottom Paste:
  text ".ProjectPCBFabRevision" at 209.188,-104.562 h1.5
  text "'.Layer_Name'" at 174.01,-104.74 h1.5
Top Solder:
  text ".ProjectPCBFabRevision" at 209.188,-104.562 h1.5
  text "'.Layer_Name'" at 174.01,-104.74 h1.5
Bottom Solder:
  text ".ProjectPCBFabRevision" at 209.188,-104.562 h1.5
  text "'.Layer_Name'" at 174.01,-104.74 h1.5
NOTES (M1):
  lines w0.1: -2.5,-2.5 53.3,-2.5 53.3,22.82 -2.5,22.82 -2.5,-2.5
  text "'.Layer_Name'" at 192.01,-104.74 h1.5
BOARD (M2):
  the board outline again, w0.1
  text ".ProjectPCBFabRevision" at 209.188,-104.562 h1.5
  text "'.Layer_Name'" at 174.01,-104.74 h1.5
REF POINTS (M3):
  text "'.Layer_Name'" at 174.01,-104.74 h1.5
FAB (M4):
  text ".ProjectPCBFabRevision" at 209.188,-104.562 h1.5
  text "'.Layer_Name'" at 174.01,-104.74 h1.5
Case (M5):
  text "'.Layer_Name'" at 174.01,-104.74 h1.5
Cover (M6):
  text "'.Layer_Name'" at 174.01,-104.74 h1.5
Terminal Block (M7):
  text "'.Layer_Name'" at 174.01,-104.74 h1.5
Route Tool Path:
  text "'.Layer_Name'" at 174.01,-104.74 h1.5
V-Cut (M9):
  text "'.Layer_Name'" at 174.01,-104.74 h1.5
Bottom Assembly:
  text "'.VariantName'" at -76.44,-88.74 h0.9
  text "ASSEMBLY VARIANT:" at -62.19,-88.74 h0.9
  text "DOCUMENT NUMBER:" at -108.44,-96.99 h1.15
  text "'.ProjectPCBAssyNumber'_ASSY-D" at -108.69,-99.99 h1.38
  text ".ProjectPCBAssyRevision" at -125.368,-104.562 h1.5
  text "'.Layer_Name'" at -90.49,-104.74 h1
Top Assembly:
  text "ASSEMBLY VARIANT:" at 146.01,-88.74 h0.9
  text "'.VariantName'" at 160.26,-88.74 h0.9
  text "DOCUMENT NUMBER:" at 192.26,-96.99 h1.15
  text "'.ProjectPCBAssyNumber'_ASSY-D" at 192.51,-99.99 h1.38
  text ".ProjectPCBAssyRevision" at 209.188,-104.562 h1.5
  text "'.Layer_Name'" at 174.01,-104.74 h1
Bottom 3D Body:
  text "'.Layer_Name'" at 174.01,-104.74 h1.15
Top 3D Body:
  text "'.Layer_Name'" at 174.01,-104.74 h1.2
Bottom Courtyard:
  text ".ProjectPCBFabRevision" at 209.188,-104.562 h1.5
  text "'.Layer_Name'" at 174.01,-104.74 h1
Top Courtyard:
  text ".ProjectPCBFabRevision" at 209.188,-104.562 h1.5
  text "'.Layer_Name'" at 174.01,-104.74 h1.1
TITLE (M16):
  lines w0.1: 145.51,-87.49 227.33,-87.49 ; 197.51,-79.99 197.51,-82.99 227.33,-82.99 ; 216.05,-104.625 216.05,-103.355 ; 216.05,-103.99 226.21,-103.99 ; 216.21,-102.79 216.21,-101.79 ; 216.21,-102.29 226.21,-102.29 ; 218.59,-104.625 218.59,-103.355 ; 221.13,-104.625 221.13,-103.355 ; 221.21,-102.59 221.21,-101.99 ; 223.67,-104.625 223.67,-103.355 ; 226.21,-104.625 226.21,-103.355 ; 226.21,-102.79 226.21,-101.79 ; 227.33,-82.99 227.33,-82.99
  lines w0.127: -148.59,-50.165 -143.51,-50.165 ; -148.59,10.16 -143.51,10.16 ; -148.59,70.485 -143.51,70.485 ; -85.09,-110.49 -85.09,-105.41 ; -85.09,125.73 -85.09,130.81 ; -21.59,-110.49 -21.59,-105.41 ; -21.59,125.73 -21.59,130.81 ; 41.91,-110.49 41.91,-105.41 ; 41.91,125.73 41.91,130.81 ; 77.47,-105.41 113.03,-105.41 ; 105.41,-110.49 105.41,-105.41 ; 105.41,125.73 105.41,130.81 ; 145.51,-105.41 145.51,-79.99 ; 145.51,-100.99 227.33,-100.99 ; 145.51,-94.99 227.33,-94.99 ; 145.51,-88.99 227.33,-88.99 ; 168.91,-110.49 168.91,-105.41 ; 168.91,125.73 168.91,130.81 ; 173.51,-105.41 173.51,-88.99 ; 191.51,-100.99 191.51,-94.99 ; 204.51,-105.41 204.51,-100.99 ; 212.01,-105.41 212.01,-94.99 ; 227.33,-74.93 227.33,-105.41 ; 227.33,-50.165 232.41,-50.165 ; 227.33,10.16 232.41,10.16 ; 227.33,70.485 232.41,70.485 ; 227.33,-105.41 227.33,-79.99 111.51,-79.99 111.51,-105.41 227.33,-105.41 ; 227.33,-105.41 -143.51,-105.41 -143.51,125.73 227.33,125.73 227.33,-105.41 ; -148.59,-110.49 232.41,-110.49 232.41,130.81 -148.59,130.81 -148.59,-110.49
  lines w0.254: 116.83,116.73 116.83,121.23 116.83,125.73 ; 129.33,116.73 129.33,121.23 129.33,125.73 ; 207.83,116.73 207.83,121.23 207.83,125.73 ; 227.33,121.23 105.83,121.23 ; 105.83,121.23 105.83,125.73 227.33,125.73 227.33,116.73 105.83,116.73 105.83,121.23
  text "1" at -117.314,127.508 h1.78
  text "2" at -53.924,127.508 h1.78
  text "3" at 9.305,127.508 h1.78
  text "4" at 72.974,127.508 h1.78
  text "5" at 136.449,127.508 h1.78
  text "6" at 200.076,127.508 h1.78
  text "REV" at 108.33,122.73 h1.52
  text "ECO" at 118.33,122.73 h1.52
  text "Comments" at 164.83,122.23 h1.52
  text "Date" at 212.83,122.23 h1.52
  text "A" at -146.685,98.476 h1.78
  text "A" at 229.235,98.476 h1.78
  text "B" at -146.685,38.024 h1.78
  text "B" at 229.235,38.024 h1.78
  text "C" at -146.685,-22.301 h1.78
  text "C" at 229.235,-22.301 h1.78
  text "PART NUMBER:" at 198.51,-81.99 h1
  text "'.ProjectpartNumber'" at 210.51,-82.24 h1.5
  text "D" at -146.685,-82.499 h1.78
  text "TITLE:" at 146.51,-82.49 h1.14
  text "D" at 229.235,-82.499 h1.78
  text "'.ProjectTitle'" at 146.51,-86.49 h2.5
  text "PCB Layout Contact:" at 146.51,-90.99 h1.15
  text "GERBER FILE:" at 174.51,-90.99 h1.15
  text ".ProjectContactPCB" at 146.51,-93.99 h1.6
  text "'.Plot_File_Name'" at 174.51,-93.99 h1.5
  text "M" at 114.51,-95.99 h15.24
  text "Project Owner:" at 146.51,-96.99 h1.15
  text "BOARD NUMBER:" at 174.51,-96.99 h1.15
  text "DATE:" at 213.21,-96.99 h1.14
  text "Microchip Technology Inc." at 113.28,-99.25 h1.78
  text ".ProjectContactOwner" at 146.51,-99.99 h1.6
  text ".ProjectPCBFabNumber" at 174.51,-99.99 h1.6
  text "'.PRINT_DATE'" at 213.21,-99.99 h1.5
  text "2355 W. Chandler Blvd." at 114.51,-101.99 h1.78
  text "LAYER NAME:" at 174.51,-102.49 h1.14
  text "10mm" at 212.51,-102.59 h0.7
  text "PCB FILE NAME:" at 146.51,-102.74 h1.15
  text "REV:" at 205.26,-102.74 h1.14
  text "400mil" at 212.41,-104.29 h0.7
  text "Chandler, AZ  85224" at 115.51,-104.49 h1.78
  text "'.PCB_FILE_NAME_NO_PATH'" at 146.51,-104.74 h1
  text "1" at -117.314,-108.712 h1.78
  text "2" at -53.924,-108.712 h1.78
  text "3" at 9.305,-108.712 h1.78
  text "4" at 72.974,-108.712 h1.78
  text "5" at 136.449,-108.712 h1.78
  text "6" at 200.076,-108.712 h1.78
Drill Drawing:
  text "DOCUMENT NUMBER:" at 192.26,-96.99 h1.15
  text "'.ProjectPCBFabNumber'_FAB-D" at 192.51,-99.99 h1.38
  text ".ProjectPCBFabRevision" at 209.188,-104.562 h1.5
TITLE MIRROR (M17):
  lines w0.1: -143.51,-87.49 -61.69,-87.49 ; -142.39,-104.625 -142.39,-103.355 ; -142.39,-103.99 -132.23,-103.99 ; -142.39,-102.79 -142.39,-101.79 ; -142.39,-102.29 -132.39,-102.29 ; -139.85,-104.625 -139.85,-103.355 ; -137.39,-102.59 -137.39,-101.99 ; -137.31,-104.625 -137.31,-103.355 ; -134.77,-104.625 -134.77,-103.355 ; -132.39,-102.79 -132.39,-101.79 ; -132.23,-104.625 -132.23,-103.355 ; -113.69,-79.99 -113.69,-82.99 -143.51,-82.99 ; -143.51,-82.99 -143.51,-82.99
  lines w0.127: -148.59,-50.165 -143.51,-50.165 ; -148.59,10.16 -143.51,10.16 ; -148.59,70.485 -143.51,70.485 ; -143.51,-100.99 -61.69,-100.99 ; -143.51,-94.99 -61.69,-94.99 ; -143.51,-88.99 -61.69,-88.99 ; -128.19,-105.41 -128.19,-94.99 ; -120.69,-105.41 -120.69,-100.99 ; -107.69,-100.99 -107.69,-94.99 ; -89.69,-105.41 -89.69,-88.99 ; -85.09,-110.49 -85.09,-105.41 ; -85.09,125.73 -85.09,130.81 ; -61.69,-105.41 -61.69,-79.99 ; -21.59,-110.49 -21.59,-105.41 ; -21.59,125.73 -21.59,130.81 ; 41.91,-110.49 41.91,-105.41 ; 41.91,125.73 41.91,130.81 ; 105.41,-110.49 105.41,-105.41 ; 105.41,125.73 105.41,130.81 ; 168.91,-110.49 168.91,-105.41 ; 168.91,125.73 168.91,130.81 ; 227.33,-50.165 232.41,-50.165 ; 227.33,10.16 232.41,10.16 ; 227.33,70.485 232.41,70.485 ; -143.51,-105.41 227.33,-105.41 227.33,125.73 -143.51,125.73 -143.51,-105.41 ; -143.51,-105.41 -27.69,-105.41 -27.69,-79.99 -143.51,-79.99 -143.51,-105.41 ; -148.59,-110.49 232.41,-110.49 232.41,130.81 -148.59,130.81 -148.59,-110.49
  lines w0.254: -143.51,121.23 -22.01,121.23 ; -124.01,116.73 -124.01,121.23 -124.01,125.73 ; -45.51,116.73 -45.51,121.23 -45.51,125.73 ; -33.01,116.73 -33.01,121.23 -33.01,125.73 ; -22.01,121.23 -22.01,125.73 -143.51,125.73 -143.51,116.73 -22.01,116.73 -22.01,121.23
  text "6" at -116.256,127.508 h1.78
  text "5" at -52.629,127.508 h1.78
  text "4" at 10.846,127.508 h1.78
  text "3" at 74.515,127.508 h1.78
  text "2" at 137.744,127.508 h1.78
  text "1" at 201.134,127.508 h1.78
  text "ECO" at -34.51,122.73 h1.52
  text "REV" at -24.51,122.73 h1.52
  text "Date" at -129.01,122.23 h1.52
  text "Comments" at -81.01,122.23 h1.52
  text "A" at -145.415,98.476 h1.78
  text "A" at 230.505,98.476 h1.78
  text "B" at -145.415,38.024 h1.78
  text "B" at 230.505,38.024 h1.78
  text "C" at -145.415,-22.301 h1.78
  text "C" at 230.505,-22.301 h1.78
  text "PART NUMBER:" at -114.69,-81.99 h1
  text "'.ProjectpartNumber'" at -126.69,-82.24 h1.5
  text "D" at -145.415,-82.499 h1.78
  text "TITLE:" at -62.69,-82.49 h1.14
  text "D" at 230.505,-82.499 h1.78
  text "'.ProjectTitle'" at -62.69,-86.49 h2.5
  text "GERBER FILE:" at -90.69,-90.99 h1.15
  text "PCB Layout Contact:" at -62.69,-90.99 h1.15
  text "'.Plot_File_Name'" at -90.69,-93.99 h1.5
  text ".ProjectContactPCB" at -62.69,-93.99 h1.6
  text "M" at -30.69,-95.99 h15.24
  text "DATE:" at -129.39,-96.99 h1.14
  text "BOARD NUMBER:" at -90.69,-96.99 h1.15
  text "Project Owner:" at -62.69,-96.99 h1.15
  text "Microchip Technology Inc." at -29.46,-99.25 h1.78
  text "'.PRINT_DATE'" at -129.39,-99.99 h1.5
  text ".ProjectPCBAssyNumber" at -90.69,-99.99 h1.6
  text ".ProjectContactOwner" at -62.69,-99.99 h1.6
  text "2355 W. Chandler Blvd." at -30.69,-101.99 h1.78
  text "LAYER NAME:" at -90.69,-102.49 h1.14
  text "10mm" at -128.69,-102.59 h0.7
  text "REV:" at -121.44,-102.74 h1.14
  text "PCB FILE NAME:" at -62.69,-102.74 h1.15
  text "400mil" at -128.59,-104.29 h0.7
  text "Chandler, AZ  85224" at -31.69,-104.49 h1.78
  text "'.PCB_FILE_NAME_NO_PATH'" at -62.69,-104.74 h1
  text "6" at -116.256,-108.712 h1.78
  text "5" at -52.629,-108.712 h1.78
  text "4" at 10.846,-108.712 h1.78
  text "3" at 74.515,-108.712 h1.78
  text "2" at 137.744,-108.712 h1.78
  text "1" at 201.134,-108.712 h1.78

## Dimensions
2.54,0 to 2.54,2.54 on Drill Drawing
0,2.54 to 2.54,2.54 on Drill Drawing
